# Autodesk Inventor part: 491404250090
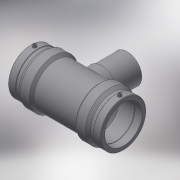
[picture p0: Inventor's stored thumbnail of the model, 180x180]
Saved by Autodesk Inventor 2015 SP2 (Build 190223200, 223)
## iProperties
Created: 2017-06
Part Number: 491404250090
Material: Generic
Description: PLASSON REDUCING TEE 250x90x250
Document SubType Name: Modeling
Designer: KIM
Mass: 15159.8 g
Surface Area: 10378.4 cm^2
Volume: 15159.8 cm^3
Density: 1 g/cm^3
Appearance: Default
Author: KIM
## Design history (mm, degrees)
derived "491404.ipt"
feature "Solid1::491404.ipt"
tag "TaggingFeature1"
body "Solid1"
other parameters: "d0" = 538, "d2" = 326, "d3" = 129, "d4" = 107.6, "d5" = 293.4, "d6" = 237.5, "d8" = 168 deg, "d10" = 51.6, "d11" = 17.2, "d13" = 538, "d14" = 17.6296, "d17" = 225, "d19" = 3.52592, "d20" = 168 deg, "d22" = 303.18, "d23" = 326, "d25" = 135 deg, "d26" = 376.6, "d29" = 152, "d30" = 15, "d31" = 215.2, "d34" = 5 deg, "d35" = 15, "d39" = 5 deg, "d41" = 4, "d42" = 14, "d43" = 0, "d45" = 4, "d46" = 6, "d47" = 0, "d48" = -235, "d51" = 0, "d52" = 72, "d54" = 0, "d55" = 293.4, "d56" = 326, "d57" = 188.3, "d58" = 135 deg, "d59" = 129, "d60" = 129, "d61" = 135 deg, "d62" = 235, "d72" = 244.79, "d73" = 122.395, "d74" = -235, "d75" = 94.5, "d77" = 0, "d78" = 72, "d80" = 0, "d82" = 72, "d83" = 0, "d84" = 3, "d85" = 0, "d86" = 43, "d87" = 297.1164, "d88" = 17.2, "d89" = 3, "d90" = 0, "L_" = 538, "L_1" = 129, "D_" = 326, "A_" = 152, "d_2" = 12, "H_" = 235
